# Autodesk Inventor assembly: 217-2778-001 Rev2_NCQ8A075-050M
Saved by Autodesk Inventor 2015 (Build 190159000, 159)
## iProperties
Created: 2014-11
Part Number: 217-2778-001 Rev2_NCQ8A075-050M
Document SubType Name: Assembly
Designer: User
Author: User
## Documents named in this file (4)
- C:\Users\User\Documents\Inventor\217-2778-001 Rev2_NCQ8A075-050M.iam
- C:\Users\User\Documents\Inventor\217-2778-NCQ8A075-050M_NCQ8 Tube_075A.ipt
- C:\Users\User\Documents\Inventor\217-2778-NCQ8A075-050M_NCQ8 Rod_075M.ipt
- C:\Users\User\Documents\Inventor\217-2778-NCQ8A075-050M_Snap Ring_075.ipt
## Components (3 placed, 3 different names)
1. 217-2778-NCQ8A075-050M_NCQ8 Tube_075A_101
2. 217-2778-NCQ8A075-050M_NCQ8 Rod_075M_102
3. 217-2778-NCQ8A075-050M_Snap Ring_075_103
